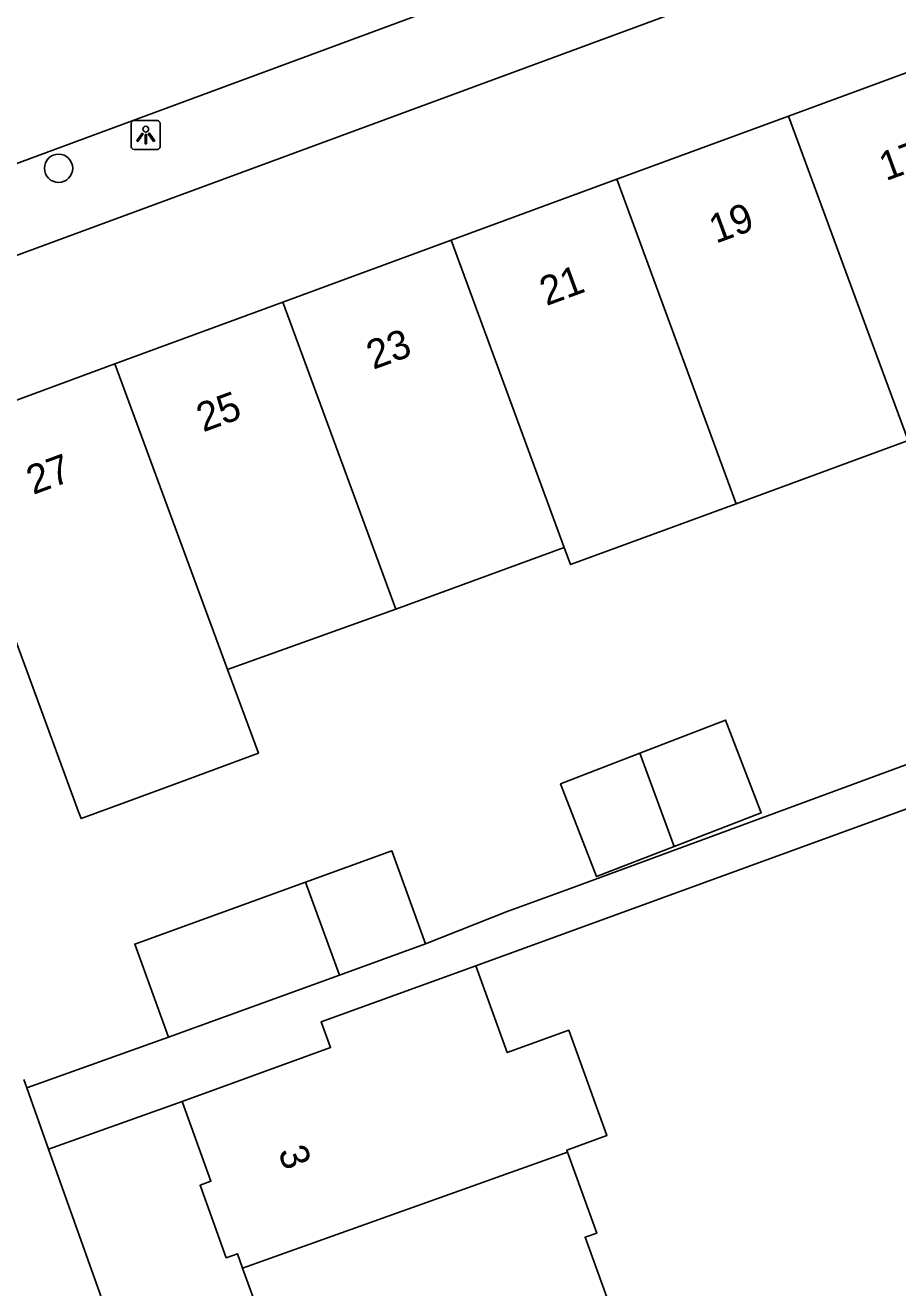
# Model space of a CAD drawing. Extents: x 161258 to 161838, y 380836 to 381727.
# Drawn here: x 161631.75 to 161661.92, y 381428.59 to 381472.25 of the extents above; entities that cross this region are included whole.
import ezdxf

# ---------------------------------------------------------------- set-up
doc = ezdxf.new("R2010")
doc.units = 0
for name, color, linetype in [('IMGEO_Boom', 7, 'Continuous'), ('IMGEO_Lichtpunt', 7, 'Continuous'), ('IMGEO_Pand', 7, 'Continuous'), ('IMGEO_Pand_nummerreeks', 7, 'Continuous'), ('IMGEO_Rijbaan_lokaal_open', 7, 'Continuous'), ('IMGEO_Voetpad_open', 7, 'Continuous')]:
    doc.layers.add(name, color=color, linetype=linetype)

msp = doc.modelspace()

# ---------------------------------------------------------------- linework, layer by layer
at = {"layer": 'IMGEO_Boom'}
msp.add_circle((161632.901, 381467.304), 0.489, dxfattribs=at)
at = {"layer": 'IMGEO_Lichtpunt'}
for p, q in [((161635.418, 381468.858), (161635.418, 381468.051)), ((161635.418, 381468.858), (161635.418, 381468.051)), ((161636.32, 381468.953), (161635.512, 381468.953)), ((161636.32, 381468.953), (161635.512, 381468.953)), ((161636.414, 381468.051), (161636.414, 381468.858)), ((161636.414, 381468.051), (161636.414, 381468.858)), ((161635.512, 381467.957), (161636.32, 381467.957)), ((161635.512, 381467.957), (161636.32, 381467.957))]:
    msp.add_line(p, q, dxfattribs=at)
for points in [[(161635.792, 381468.522), (161635.831, 381468.494), (161635.643, 381468.232), (161635.605, 381468.259), (161635.792, 381468.522)], [(161635.894, 381468.474), (161635.941, 381468.474), (161635.941, 381468.152), (161635.894, 381468.152), (161635.894, 381468.474)], [(161636.004, 381468.494), (161636.042, 381468.521), (161636.229, 381468.259), (161636.19, 381468.231), (161636.004, 381468.494)]]:
    msp.add_lwpolyline(points, dxfattribs=at)
msp.add_circle((161635.917, 381468.656), 0.0994, dxfattribs=at)
for centre, start, end in [((161635.512, 381468.858), 90, 180), ((161635.512, 381468.858), 90, 180), ((161636.32, 381468.858), 0, 90), ((161636.32, 381468.858), 0, 90), ((161635.512, 381468.051), 180, 270), ((161635.512, 381468.051), 180, 270), ((161636.32, 381468.051), 270, 0), ((161636.32, 381468.051), 270, 360)]:
    msp.add_arc(centre, 0.0946, start, end, dxfattribs=at)
at = {"layer": 'IMGEO_Pand'}
for points in [[(161658.144, 381469.111), (161663.871, 381471.218)], [(161652.21, 381466.928), (161658.144, 381469.111)], [(161662.284, 381457.893), (161660.939, 381461.538), (161658.144, 381469.111)], [(161646.477, 381464.819), (161652.21, 381466.928)], [(161652.21, 381466.928), (161656.338, 381455.706)], [(161640.663, 381462.68), (161646.477, 381464.819)], [(161646.477, 381464.819), (161650.384, 381454.194)], [(161634.845, 381460.539), (161640.663, 381462.68)], [(161644.57, 381452.056), (161640.663, 381462.68)], [(161638.75, 381449.971), (161639.816, 381447.073), (161637.103, 381446.076), (161635.232, 381445.389), (161633.679, 381444.818), (161633.593, 381445.054), (161632.008, 381449.363), (161631.512, 381450.712), (161629.712, 381455.604), (161628.803, 381455.27), (161627.947, 381457.598), (161628.856, 381457.932), (161628.725, 381458.288), (161634.845, 381460.539)], [(161634.845, 381460.539), (161638.75, 381449.971)], [(161662.284, 381457.893), (161656.338, 381455.706)], [(161656.338, 381455.706), (161650.604, 381453.597), (161650.384, 381454.194)], [(161650.384, 381454.194), (161644.57, 381452.056)], [(161644.57, 381452.056), (161638.75, 381449.971)], [(161653.003, 381447.074), (161655.965, 381448.221), (161657.204, 381445.019), (161654.188, 381443.851)], [(161654.188, 381443.851), (161651.506, 381442.813), (161650.266, 381446.014), (161653.003, 381447.074)], [(161654.188, 381443.851), (161653.003, 381447.074)], [(161641.438, 381442.614), (161644.43, 381443.699), (161645.597, 381440.484)], [(161636.704, 381437.258), (161635.537, 381440.474), (161641.438, 381442.614)], [(161641.438, 381442.614), (161642.618, 381439.403)], [(161645.597, 381440.484), (161642.618, 381439.403)], [(161637.173, 381435.03), (161642.312, 381436.894), (161641.987, 381437.79), (161647.334, 381439.729)], [(161647.334, 381439.729), (161648.421, 381436.726), (161650.549, 381437.497), (161651.868, 381433.855), (161650.475, 381433.348), (161650.5, 381433.278)], [(161642.618, 381439.403), (161636.704, 381437.258)], [(161639.267, 381429.267), (161639.085, 381429.769), (161638.703, 381429.63), (161637.794, 381432.137), (161638.172, 381432.274), (161637.173, 381435.03)], [(161650.5, 381433.278), (161639.267, 381429.267)], [(161650.5, 381433.278), (161651.513, 381430.483), (161651.111, 381430.337), (161652.116, 381427.564)], [(161641.325, 381423.633), (161641.098, 381424.258), (161640.441, 381424.374), (161639.732, 381426.332), (161640.15, 381426.829), (161639.267, 381429.267)]]:
    msp.add_lwpolyline(points, dxfattribs=at)
at = {"layer": 'IMGEO_Rijbaan_lokaal_open'}
msp.add_lwpolyline([(161619.919, 381463.183), (161625.703, 381465.347), (161649.734, 381474.239), (161657.089, 381476.959)], dxfattribs=at)
at = {"layer": 'IMGEO_Voetpad_open'}
for points in [[(161692.567, 381486.83), (161622.485, 381460.994)], [(161645.597, 381440.484), (161648.418, 381441.597), (161650.576, 381442.391), (161665.897, 381448.031), (161665.866, 381448.114)], [(161673.803, 381429.149), (161672.696, 381428.746), (161672.606, 381428.993), (161668.469, 381440.343), (161666.191, 381446.595), (161647.334, 381439.729)], [(161631.8, 381435.51), (161636.704, 381437.258)], [(161631.7, 381435.792), (161631.8, 381435.51)], [(161631.8, 381435.51), (161632.557, 381433.385)], [(161637.173, 381435.03), (161632.557, 381433.385)], [(161632.557, 381433.385), (161638.239, 381417.444), (161637.547, 381412.742), (161634.273, 381385.117)]]:
    msp.add_lwpolyline(points, dxfattribs=at)

# ---------------------------------------------------------------- texts
at = {"layer": 'IMGEO_Pand_nummerreeks'}
for s, rotation, p in [('17', 20.1977, (161661.514, 381466.856)), ('19', 20.1977, (161655.632, 381464.692)), ('21', 20.1977, (161649.772, 381462.536)), ('23', 20.1977, (161643.785, 381460.333)), ('25', 20.1977, (161637.904, 381458.17)), ('27', 20.1968, (161632.023, 381456.006)), ('3', 289.9846, (161640.483, 381433.301))]:
    msp.add_text(s, height=1, rotation=rotation, dxfattribs=at).set_placement(p)

doc.saveas('drawing.dxf')
